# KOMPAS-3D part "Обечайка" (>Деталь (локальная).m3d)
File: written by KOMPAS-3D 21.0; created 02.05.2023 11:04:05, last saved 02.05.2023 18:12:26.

Document properties: Автор: pc; Полное имя файла: C:\Users\Константин Сергеев\AppData\Local\Temp\KOMPAS-3D\ktfb-5bc4-7143-8fb3\_Деталь (локальная).m3d

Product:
- Part/product: Обечайка
    Масса: 0.245959

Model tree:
1. Эскиз:1
2. Обечайка:1
     Расстояние 1 = 50
3. Сгиб(1) - Обечайка:1
     Радиус сгиба = 100; Коэффициент = 0.4; Величина сгиба = 10; Зазор = 1
4. Плоскость, касательная в точке:1  (with: Обечайка:1)
5. Разогнуть:1  (with: Обечайка:1)
6. Эскиз:2  (with: Обечайка:1)
7. Вырез в листовом теле:1
     Глубина выреза = 10
8. Согнуть:1  (with: Обечайка:1)
9. Отверстие:1  (with: Обечайка:1)
     Глубина выреза = 40; Диаметр отверстия = 2.3; Угол конуса дна = 118; Угол 1 = 30; Расстояние 2 = -25
10. Массив по концентрической сетке:1  (with: Отверстие:1)  (17 pattern instances)
     Шаг 2 = 360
